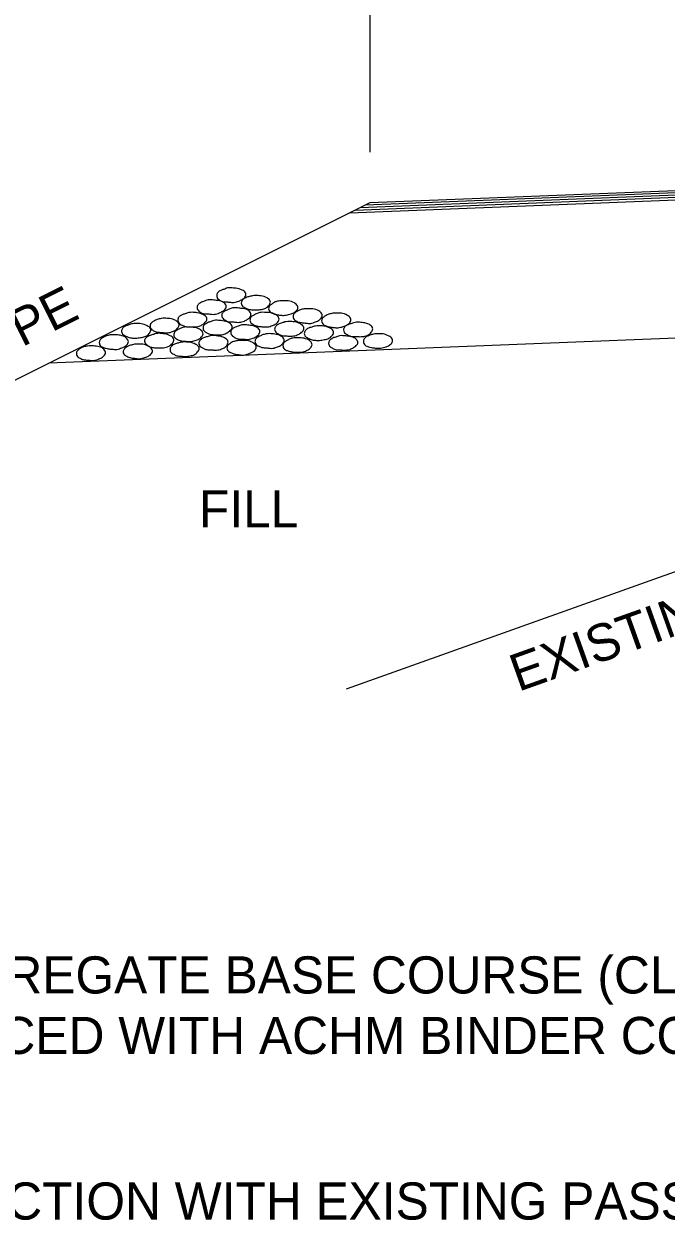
# Model space of a CAD drawing. Extents: x -2842 to 2681, y -2139 to 474.
# Drawn here: x 1394.8 to 1498.5, y -124.9 to 68.4 of the extents above; entities that cross this region are included whole.
import ezdxf

# ---------------------------------------------------------------- set-up
doc = ezdxf.new("R2010")
doc.units = 0
doc.layers.add('R_Grid', color=7, linetype='Continuous')

msp = doc.modelspace()

# ---------------------------------------------------------------- linework, layer by layer
at = {"layer": 'R_Grid'}
for p, q in [((1450.73, 47.63), (1450.73, 200.44)), ((1448.3, 38.28), (2093.98, 64.03)), ((1449.13, 38.68), (2093.27, 64.39)), ((1449.98, 39.13), (2092.52, 64.76)), ((1450.73, 39.48), (2091.83, 65.1)), ((1447.46, 37.85), (2094.71, 63.67)), ((1326.55, -22.57), (1450.73, 39.48)), ((1398.89, 13.57), (1650.04, 23.58)), ((1594.52, 13.63), (1446.87, -39.13))]:
    msp.add_line(p, q, dxfattribs=at)
for points in [[(1428.25, 25.72), (1429.08, 25.63), (1430.07, 25.35), (1430.61, 24.91), (1430.68, 24.61), (1430.43, 24.11), (1430.11, 23.87), (1429.54, 23.56), (1428.76, 23.36), (1428.34, 23.36), (1427.74, 23.43), (1427.02, 23.47), (1426.52, 23.68), (1426.03, 24.14), (1425.97, 24.44), (1426.11, 24.91), (1426.48, 25.21), (1426.83, 25.37), (1427.39, 25.56), (1427.71, 25.7), (1428.25, 25.72)], [(1425.09, 23.79), (1425.94, 23.68), (1426.9, 23.44), (1427.44, 22.97), (1427.52, 22.68), (1427.25, 22.17), (1426.94, 21.95), (1426.39, 21.65), (1425.59, 21.43), (1425.18, 21.43), (1424.57, 21.5), (1423.86, 21.54), (1423.34, 21.76), (1422.88, 22.21), (1422.79, 22.53), (1422.96, 22.98), (1423.33, 23.3), (1423.68, 23.47), (1424.23, 23.64), (1424.57, 23.76), (1425.09, 23.79)], [(1432.26, 24.48), (1433.11, 24.41), (1434.09, 24.09), (1434.57, 23.66), (1434.64, 23.41), (1434.39, 22.86), (1434.16, 22.6), (1433.58, 22.32), (1432.81, 22.16), (1432.38, 22.13), (1431.76, 22.15), (1431.05, 22.26), (1430.54, 22.5), (1430.02, 22.89), (1429.94, 23.22), (1430.08, 23.66), (1430.49, 24.02), (1430.83, 24.19), (1431.4, 24.34), (1431.74, 24.41), (1432.26, 24.48)], [(1436.67, 23.62), (1437.49, 23.6), (1438.52, 23.27), (1438.99, 22.79), (1439.08, 22.5), (1438.8, 21.99), (1438.53, 21.76), (1437.98, 21.52), (1437.18, 21.29), (1436.74, 21.26), (1436.12, 21.31), (1435.45, 21.43), (1434.93, 21.64), (1434.43, 22.03), (1434.35, 22.34), (1434.52, 22.8), (1434.89, 23.09), (1435.23, 23.36), (1435.79, 23.53), (1436.14, 23.6), (1436.67, 23.62)], [(1422.01, 21.76), (1422.84, 21.68), (1423.81, 21.37), (1424.32, 20.96), (1424.4, 20.65), (1424.12, 20.16), (1423.83, 19.88), (1423.32, 19.58), (1422.52, 19.41), (1422.11, 19.41), (1421.47, 19.4), (1420.77, 19.51), (1420.24, 19.75), (1419.75, 20.2), (1419.69, 20.47), (1419.83, 20.97), (1420.19, 21.26), (1420.58, 21.43), (1421.16, 21.61), (1421.47, 21.71), (1422.01, 21.76)], [(1429.11, 22.49), (1429.94, 22.39), (1430.94, 22.15), (1431.43, 21.66), (1431.5, 21.39), (1431.26, 20.87), (1430.96, 20.64), (1430.43, 20.34), (1429.64, 20.14), (1429.21, 20.14), (1428.58, 20.2), (1427.88, 20.23), (1427.37, 20.47), (1426.87, 20.92), (1426.78, 21.23), (1426.94, 21.69), (1427.32, 21.98), (1427.7, 22.15), (1428.25, 22.36), (1428.58, 22.47), (1429.11, 22.49)], [(1433.66, 21.74), (1434.48, 21.71), (1435.5, 21.4), (1435.97, 20.93), (1436.04, 20.64), (1435.79, 20.13), (1435.55, 19.9), (1434.96, 19.62), (1434.19, 19.4), (1433.76, 19.4), (1433.12, 19.44), (1432.44, 19.55), (1431.93, 19.74), (1431.41, 20.17), (1431.34, 20.49), (1431.47, 20.96), (1431.87, 21.24), (1432.23, 21.44), (1432.79, 21.66), (1433.12, 21.74), (1433.66, 21.74)], [(1440.63, 22.33), (1441.49, 22.29), (1442.46, 21.98), (1442.94, 21.52), (1443.02, 21.21), (1442.75, 20.72), (1442.53, 20.49), (1441.94, 20.23), (1441.15, 19.97), (1440.74, 19.97), (1440.11, 20.03), (1439.45, 20.11), (1438.88, 20.3), (1438.37, 20.75), (1438.29, 21.06), (1438.45, 21.52), (1438.82, 21.82), (1439.21, 22.03), (1439.76, 22.24), (1440.11, 22.3), (1440.63, 22.33)], [(1445.26, 21.63), (1446.1, 21.61), (1447.06, 21.26), (1447.55, 20.83), (1447.63, 20.54), (1447.39, 20), (1447.11, 19.78), (1446.57, 19.51), (1445.76, 19.29), (1445.35, 19.25), (1444.73, 19.32), (1444.04, 19.42), (1443.49, 19.62), (1442.99, 20.03), (1442.91, 20.35), (1443.07, 20.8), (1443.44, 21.14), (1443.82, 21.35), (1444.38, 21.52), (1444.74, 21.61), (1445.26, 21.63)], [(1412.94, 19.94), (1413.77, 19.9), (1414.74, 19.55), (1415.26, 19.15), (1415.33, 18.88), (1415.05, 18.33), (1414.8, 18.05), (1414.22, 17.81), (1413.46, 17.63), (1413.06, 17.59), (1412.39, 17.6), (1411.68, 17.73), (1411.19, 17.97), (1410.69, 18.36), (1410.61, 18.67), (1410.76, 19.15), (1411.13, 19.48), (1411.51, 19.64), (1412.07, 19.83), (1412.39, 19.9), (1412.94, 19.94)], [(1417.53, 20.79), (1418.39, 20.73), (1419.35, 20.42), (1419.84, 19.96), (1419.9, 19.67), (1419.66, 19.18), (1419.39, 18.94), (1418.84, 18.65), (1418.05, 18.44), (1417.63, 18.44), (1417, 18.5), (1416.33, 18.56), (1415.79, 18.76), (1415.27, 19.2), (1415.21, 19.53), (1415.35, 19.97), (1415.72, 20.27), (1416.09, 20.49), (1416.68, 20.68), (1417, 20.76), (1417.53, 20.79)], [(1421.37, 19.38), (1422.18, 19.32), (1423.19, 19.04), (1423.69, 18.56), (1423.76, 18.27), (1423.51, 17.77), (1423.26, 17.54), (1422.67, 17.26), (1421.91, 17.04), (1421.45, 17.04), (1420.82, 17.08), (1420.13, 17.17), (1419.62, 17.37), (1419.11, 17.81), (1419.04, 18.12), (1419.2, 18.58), (1419.58, 18.88), (1419.94, 19.08), (1420.5, 19.29), (1420.82, 19.37), (1421.37, 19.38)], [(1426.05, 20.47), (1426.89, 20.39), (1427.9, 20.09), (1428.4, 19.64), (1428.49, 19.37), (1428.22, 18.85), (1427.95, 18.63), (1427.36, 18.29), (1426.6, 18.12), (1426.16, 18.12), (1425.53, 18.14), (1424.84, 18.21), (1424.32, 18.48), (1423.83, 18.89), (1423.76, 19.22), (1423.92, 19.67), (1424.3, 19.97), (1424.66, 20.14), (1425.18, 20.3), (1425.52, 20.42), (1426.05, 20.47)], [(1430.58, 19.75), (1431.41, 19.64), (1432.38, 19.38), (1432.87, 18.91), (1432.95, 18.63), (1432.69, 18.12), (1432.44, 17.89), (1431.87, 17.59), (1431.09, 17.38), (1430.66, 17.38), (1430.04, 17.42), (1429.33, 17.48), (1428.8, 17.73), (1428.31, 18.17), (1428.24, 18.49), (1428.37, 18.93), (1428.75, 19.23), (1429.14, 19.41), (1429.72, 19.6), (1430.04, 19.72), (1430.58, 19.75)], [(1437.69, 20.28), (1438.53, 20.21), (1439.48, 19.9), (1439.97, 19.45), (1440.05, 19.2), (1439.81, 18.65), (1439.54, 18.41), (1438.97, 18.1), (1438.17, 17.92), (1437.77, 17.92), (1437.15, 17.93), (1436.46, 18.01), (1435.92, 18.27), (1435.4, 18.69), (1435.32, 19.04), (1435.49, 19.48), (1435.86, 19.79), (1436.23, 19.94), (1436.79, 20.13), (1437.18, 20.24), (1437.69, 20.28)], [(1442.44, 19.58), (1443.27, 19.54), (1444.26, 19.2), (1444.75, 18.77), (1444.82, 18.52), (1444.57, 17.95), (1444.33, 17.71), (1443.74, 17.44), (1442.96, 17.26), (1442.55, 17.22), (1441.92, 17.23), (1441.2, 17.36), (1440.7, 17.6), (1440.2, 17.98), (1440.11, 18.33), (1440.27, 18.77), (1440.63, 19.12), (1441.03, 19.28), (1441.58, 19.45), (1441.9, 19.54), (1442.44, 19.58)], [(1448.82, 20.17), (1449.65, 20.08), (1450.61, 19.78), (1451.1, 19.32), (1451.16, 19.06), (1450.93, 18.54), (1450.68, 18.27), (1450.1, 17.97), (1449.29, 17.82), (1448.89, 17.82), (1448.27, 17.84), (1447.58, 17.89), (1447.03, 18.15), (1446.52, 18.58), (1446.45, 18.9), (1446.59, 19.36), (1446.98, 19.66), (1447.36, 19.83), (1447.91, 20), (1448.3, 20.11), (1448.82, 20.17)], [(1409.32, 18.12), (1410.14, 18.07), (1411.15, 17.78), (1411.63, 17.29), (1411.71, 17.02), (1411.46, 16.49), (1411.2, 16.27), (1410.64, 16.02), (1409.85, 15.77), (1409.42, 15.77), (1408.78, 15.81), (1408.09, 15.94), (1407.57, 16.11), (1407.07, 16.53), (1407.01, 16.87), (1407.14, 17.32), (1407.54, 17.62), (1407.91, 17.84), (1408.46, 18.02), (1408.78, 18.1), (1409.32, 18.12)], [(1416.71, 18.36), (1417.52, 18.27), (1418.48, 17.97), (1418.98, 17.54), (1419.04, 17.25), (1418.82, 16.74), (1418.54, 16.46), (1418, 16.18), (1417.17, 16.02), (1416.76, 16.02), (1416.12, 16.03), (1415.43, 16.1), (1414.91, 16.34), (1414.42, 16.79), (1414.32, 17.11), (1414.48, 17.57), (1414.84, 17.85), (1415.24, 18.01), (1415.8, 18.19), (1416.15, 18.31), (1416.71, 18.36)], [(1425.46, 18.01), (1426.28, 17.92), (1427.25, 17.63), (1427.74, 17.18), (1427.81, 16.91), (1427.58, 16.4), (1427.32, 16.13), (1426.76, 15.83), (1425.96, 15.66), (1425.53, 15.66), (1424.9, 15.68), (1424.23, 15.76), (1423.69, 16.02), (1423.17, 16.43), (1423.09, 16.78), (1423.26, 17.21), (1423.64, 17.52), (1424.01, 17.69), (1424.57, 17.85), (1424.92, 17.97), (1425.46, 18.01)], [(1434.5, 18.31), (1435.33, 18.24), (1436.32, 17.92), (1436.79, 17.47), (1436.87, 17.17), (1436.6, 16.68), (1436.38, 16.45), (1435.81, 16.19), (1435.02, 15.94), (1434.59, 15.94), (1433.96, 16.01), (1433.28, 16.08), (1432.75, 16.27), (1432.22, 16.72), (1432.15, 17.04), (1432.31, 17.48), (1432.69, 17.8), (1433.07, 17.98), (1433.63, 18.19), (1433.96, 18.27), (1434.5, 18.31)], [(1438.96, 17.63), (1439.8, 17.59), (1440.81, 17.28), (1441.29, 16.8), (1441.37, 16.52), (1441.12, 16.02), (1440.87, 15.78), (1440.29, 15.5), (1439.51, 15.3), (1439.08, 15.3), (1438.45, 15.34), (1437.75, 15.44), (1437.25, 15.61), (1436.72, 16.06), (1436.66, 16.37), (1436.8, 16.82), (1437.2, 17.12), (1437.56, 17.33), (1438.11, 17.55), (1438.45, 17.62), (1438.96, 17.63)], [(1446.31, 17.98), (1447.18, 17.89), (1448.15, 17.64), (1448.67, 17.17), (1448.76, 16.9), (1448.5, 16.37), (1448.22, 16.15), (1447.62, 15.83), (1446.86, 15.64), (1446.44, 15.64), (1445.81, 15.69), (1445.09, 15.73), (1444.59, 15.99), (1444.11, 16.42), (1444.03, 16.74), (1444.18, 17.18), (1444.55, 17.49), (1444.9, 17.66), (1445.47, 17.85), (1445.8, 17.98), (1446.31, 17.98)], [(1451.99, 18.29), (1452.82, 18.27), (1453.8, 17.91), (1454.28, 17.49), (1454.36, 17.2), (1454.12, 16.66), (1453.84, 16.43), (1453.32, 16.18), (1452.49, 15.97), (1452.08, 15.94), (1451.47, 15.99), (1450.76, 16.1), (1450.22, 16.28), (1449.72, 16.7), (1449.65, 17.02), (1449.8, 17.47), (1450.17, 17.82), (1450.56, 18.01), (1451.13, 18.19), (1451.48, 18.27), (1451.99, 18.29)], [(1405.62, 16.34), (1406.5, 16.27), (1407.46, 15.99), (1407.94, 15.5), (1408.02, 15.24), (1407.77, 14.72), (1407.52, 14.5), (1406.95, 14.23), (1406.16, 13.98), (1405.74, 13.98), (1405.11, 14.03), (1404.43, 14.11), (1403.91, 14.33), (1403.39, 14.75), (1403.31, 15.08), (1403.47, 15.52), (1403.83, 15.83), (1404.2, 16.06), (1404.78, 16.24), (1405.11, 16.31), (1405.62, 16.34)], [(1413.23, 16.62), (1414.06, 16.59), (1415.03, 16.24), (1415.5, 15.81), (1415.6, 15.52), (1415.35, 14.98), (1415.08, 14.75), (1414.55, 14.5), (1413.74, 14.29), (1413.31, 14.24), (1412.68, 14.32), (1412.01, 14.43), (1411.46, 14.65), (1410.95, 15.03), (1410.87, 15.35), (1411.02, 15.8), (1411.41, 16.13), (1411.78, 16.34), (1412.33, 16.5), (1412.7, 16.59), (1413.23, 16.62)], [(1420.75, 16.97), (1421.58, 16.91), (1422.6, 16.57), (1423.07, 16.16), (1423.13, 15.91), (1422.89, 15.35), (1422.65, 15.08), (1422.05, 14.8), (1421.28, 14.66), (1420.86, 14.63), (1420.24, 14.65), (1419.52, 14.74), (1419.02, 14.98), (1418.51, 15.39), (1418.43, 15.7), (1418.59, 16.16), (1418.96, 16.49), (1419.34, 16.66), (1419.87, 16.83), (1420.22, 16.91), (1420.75, 16.97)], [(1429.97, 17.22), (1430.78, 17.2), (1431.79, 16.87), (1432.26, 16.43), (1432.35, 16.15), (1432.1, 15.6), (1431.82, 15.39), (1431.3, 15.13), (1430.49, 14.88), (1430.05, 14.84), (1429.42, 14.92), (1428.75, 15.04), (1428.21, 15.26), (1427.7, 15.64), (1427.62, 15.97), (1427.78, 16.42), (1428.17, 16.76), (1428.53, 16.97), (1429.1, 17.12), (1429.43, 17.2), (1429.97, 17.22)]]:
    msp.add_spline(points, degree=3, dxfattribs=at)

# ---------------------------------------------------------------- texts
for s, rotation, p in [('DESIGN SLOPE', 26.565, (1350.66, -5.85)), ('EXISTING SLOPE', 19.6609, (1474.67, -39.59))]:
    msp.add_text(s, height=6, rotation=rotation, dxfattribs=at).set_placement(p)
for s, p in [('FILL', (1423.1, -13.01)), ('* 7" AGGREGATE BASE COURSE (CLASS 7)', (1359.29, -88.31)), ('TO BE REPLACED WITH ACHM BINDER COURSE (1")', (1338.29, -98.09)), ('** DENOTES SECTION WITH EXISTING PASSING LANE', (1331.81, -124.84))]:
    msp.add_text(s, height=6, dxfattribs=at).set_placement(p)

doc.saveas('drawing.dxf')
